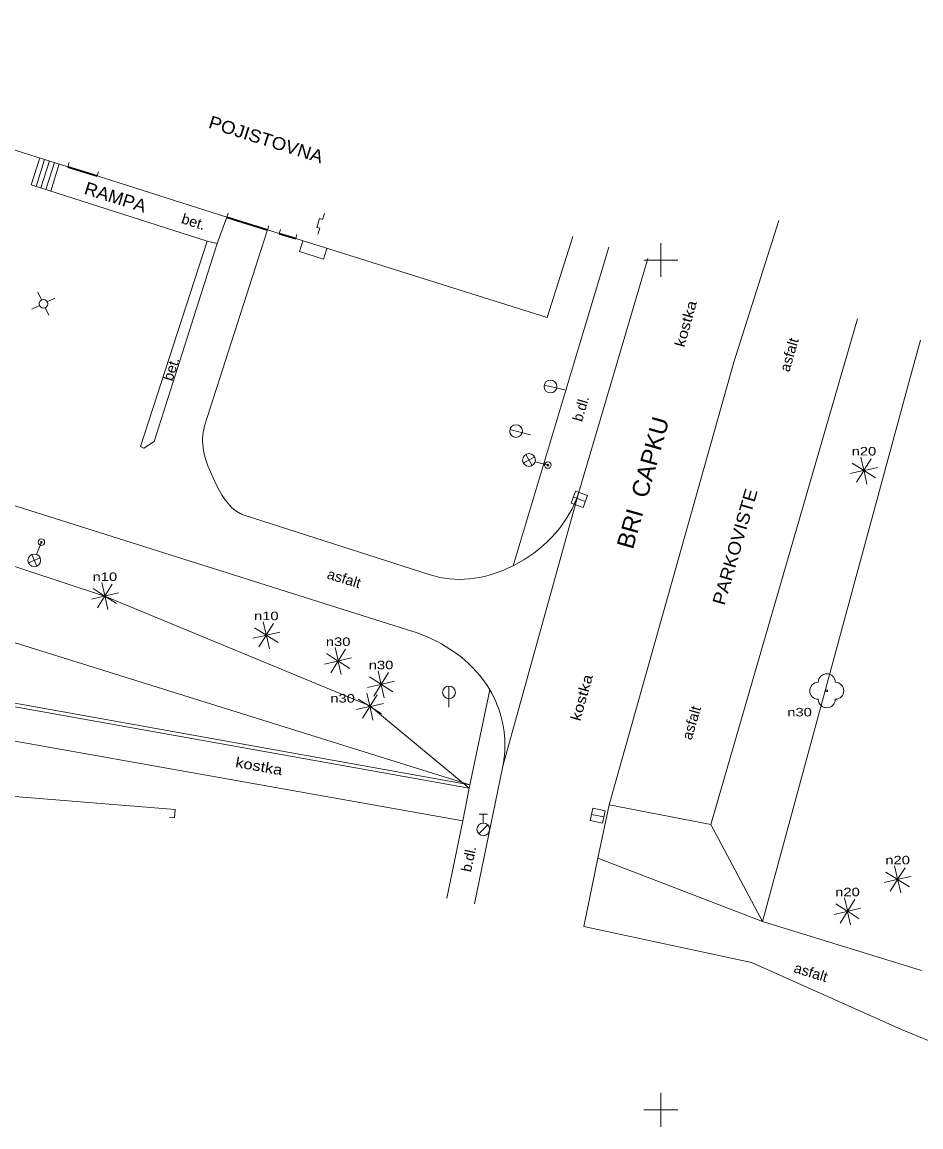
# Model space of a CAD drawing. Extents: x -670514 to -669423, y -1130798 to -1130123.
# Drawn here: x -670187.6 to -670134.7, y -1130251 to -1130186 of the extents above; entities that cross this region are included whole.
import ezdxf
from ezdxf.enums import TextEntityAlignment as Align

# ---------------------------------------------------------------- set-up
doc = ezdxf.new("R2010")
doc.units = 0
doc.header["$LTSCALE"] = 0.24
for name, color, linetype, lineweight in [('10', 7, 'Continuous', 13), ('11', 7, 'Continuous', 13), ('14', 7, 'Continuous', 13), ('22', 7, 'Continuous', 13), ('24', 7, 'Continuous', 13), ('27', 7, 'Continuous', 13), ('28', 7, 'Continuous', 13), ('31', 7, 'Continuous', 13), ('33', 7, 'Continuous', 13), ('45', 7, 'Continuous', 13), ('5', 7, 'Continuous', 13), ('6', 7, 'Continuous', 13), ('61', 7, 'Continuous', 13), ('9', 7, 'Continuous', 13)]:
    doc.layers.add(name, color=color, linetype=linetype, lineweight=lineweight)
for name, color, linetype in [('40', 7, 'Continuous'), ('41', 7, 'Continuous'), ('42', 7, 'Continuous')]:
    doc.layers.add(name, color=color, linetype=linetype)

msp = doc.modelspace()

# ---------------------------------------------------------------- linework, layer by layer
at = {"layer": '10'}
for p, q in [((-670186.532, -1130193.989), (-670187.033, -1130195.579)), ((-670186.245, -1130194.079), (-670186.746, -1130195.671)), ((-670185.959, -1130194.169), (-670186.461, -1130195.762)), ((-670185.673, -1130194.259), (-670186.175, -1130195.853)), ((-670185.387, -1130194.349), (-670185.89, -1130195.944)), ((-670176.687, -1130198.883), (-670187.033, -1130195.579)), ((-670173.137, -1130198.222), (-670176.84, -1130209.76)), ((-670153.056, -1130199.244), (-670154.502, -1130204.064)), ((-670150.763, -1130199.909), (-670152.213, -1130204.825)), ((-670138.43, -1130203.465), (-670139.173, -1130206.028)), ((-670154.502, -1130204.064), (-670158.68, -1130217.989)), ((-670152.213, -1130204.825), (-670154.821, -1130213.668)), ((-670164.577, -1130221.854), (-670216.254, -1130205.533)), ((-670139.173, -1130206.028), (-670147.058, -1130233.212)), ((-670174.503, -1130215.016), (-670163.562, -1130218.517)), ((-670190.705, -1130225.799), (-670161.27, -1130231.071)), ((-670160.061, -1130225.279), (-670161.27, -1130231.071)), ((-670190.834, -1130227.796), (-670161.644, -1130232.991)), ((-670160.957, -1130237.88), (-670159.28, -1130229.771)), ((-670153.024, -1130232.058), (-670147.058, -1130233.212)), ((-670162.586, -1130237.543), (-670161.644, -1130232.991))]:
    msp.add_line(p, q, dxfattribs=at)
for points in [[(-670180.604, -1130210.977), (-670176.687, -1130198.883), (-670176.091, -1130199.03), (-670175.528, -1130197.478)], [(-670180.604, -1130210.977), (-670180.416, -1130211.077), (-670179.812, -1130210.676), (-670176.091, -1130199.03)], [(-670154.526, -1130239.21), (-670153.696, -1130235.197), (-670153.024, -1130232.058)]]:
    msp.add_lwpolyline(points, dxfattribs=at)
for points in [[(-670176.84, -1130209.76), (-670176.921, -1130210.134), (-670176.254, -1130212.991), (-670174.734, -1130214.913), (-670174.503, -1130215.016)], [(-670163.562, -1130218.517), (-670163.28, -1130218.602), (-670158.68, -1130217.989), (-670154.944, -1130214.012), (-670154.821, -1130213.668)], [(-670164.577, -1130221.854), (-670164.092, -1130222.027), (-670160.061, -1130225.279), (-670159.179, -1130228.952), (-670159.28, -1130229.771)]]:
    msp.add_spline(points, degree=3, dxfattribs=at)
at = {"layer": '11'}
for p, q in [((-670143.047, -1130197.677), (-670145.702, -1130206.019)), ((-670145.702, -1130206.019), (-670153.024, -1130232.058)), ((-670154.821, -1130213.668), (-670159.28, -1130229.771)), ((-670161.27, -1130231.071), (-670161.644, -1130232.991))]:
    msp.add_line(p, q, dxfattribs=at)
at = {"layer": '14'}
for p, q in [((-670134.721, -1130204.715), (-670135.399, -1130207.213)), ((-670135.399, -1130207.213), (-670144.008, -1130238.917)), ((-670192.5, -1130221.111), (-670161.234, -1130230.874)), ((-670147.058, -1130233.212), (-670144.008, -1130238.917)), ((-670153.696, -1130235.197), (-670144.008, -1130238.917)), ((-670144.008, -1130238.917), (-670134.666, -1130241.791)), ((-670135.841, -1130245.268), (-670131.45, -1130247.085))]:
    msp.add_line(p, q, dxfattribs=at)
for points in [[(-670216.436, -1130208.635), (-670182.668, -1130219.789), (-670167.119, -1130226.229), (-670161.27, -1130231.071)], [(-670154.526, -1130239.21), (-670144.66, -1130241.33), (-670135.841, -1130245.268)]]:
    msp.add_lwpolyline(points, dxfattribs=at)
at = {"layer": '22'}
for p, q in [((-670138.079, -1130212.364), (-670138.735, -1130211.95)), ((-670138.053, -1130212.344), (-670138.225, -1130211.59)), ((-670137.611, -1130211.694), (-670138.025, -1130212.35)), ((-670138.839, -1130212.564), (-670138.085, -1130212.392)), ((-670138.065, -1130212.418), (-670138.479, -1130213.074)), ((-670138.037, -1130212.424), (-670137.865, -1130213.178)), ((-670137.355, -1130212.818), (-670138.011, -1130212.404)), ((-670138.005, -1130212.376), (-670137.251, -1130212.204)), ((-670182.736, -1130219.749), (-670183.392, -1130219.335)), ((-670182.71, -1130219.729), (-670182.882, -1130218.975)), ((-670182.268, -1130219.079), (-670182.682, -1130219.735)), ((-670183.496, -1130219.949), (-670182.742, -1130219.777)), ((-670182.722, -1130219.803), (-670183.136, -1130220.459)), ((-670182.694, -1130219.809), (-670182.522, -1130220.563)), ((-670182.012, -1130220.203), (-670182.668, -1130219.789)), ((-670182.662, -1130219.761), (-670181.908, -1130219.589)), ((-670173.214, -1130222.033), (-670173.386, -1130221.279)), ((-670173.24, -1130222.053), (-670173.896, -1130221.639)), ((-670172.772, -1130221.383), (-670173.186, -1130222.039)), ((-670173.166, -1130222.065), (-670172.412, -1130221.893)), ((-670174, -1130222.253), (-670173.246, -1130222.081)), ((-670173.226, -1130222.107), (-670173.64, -1130222.763)), ((-670173.198, -1130222.113), (-670173.026, -1130222.867)), ((-670172.516, -1130222.507), (-670173.172, -1130222.093)), ((-670169.012, -1130223.573), (-670169.668, -1130223.159)), ((-670168.986, -1130223.553), (-670169.158, -1130222.799)), ((-670168.544, -1130222.903), (-670168.958, -1130223.559)), ((-670169.772, -1130223.773), (-670169.018, -1130223.601)), ((-670168.998, -1130223.627), (-670169.412, -1130224.283)), ((-670168.97, -1130223.633), (-670168.798, -1130224.387)), ((-670168.288, -1130224.027), (-670168.944, -1130223.613)), ((-670168.938, -1130223.585), (-670168.184, -1130223.413)), ((-670166.486, -1130224.941), (-670167.142, -1130224.527)), ((-670166.46, -1130224.921), (-670166.632, -1130224.167)), ((-670166.018, -1130224.271), (-670166.432, -1130224.927)), ((-670167.246, -1130225.141), (-670166.492, -1130224.969)), ((-670166.472, -1130224.995), (-670166.886, -1130225.651)), ((-670166.444, -1130225.001), (-670166.272, -1130225.755)), ((-670165.762, -1130225.395), (-670166.418, -1130224.981)), ((-670166.412, -1130224.953), (-670165.658, -1130224.781)), ((-670167.143, -1130226.248), (-670167.799, -1130225.834)), ((-670167.117, -1130226.228), (-670167.289, -1130225.474)), ((-670166.675, -1130225.578), (-670167.089, -1130226.234)), ((-670167.903, -1130226.448), (-670167.149, -1130226.276)), ((-670167.129, -1130226.302), (-670167.543, -1130226.958)), ((-670167.101, -1130226.308), (-670166.929, -1130227.062)), ((-670166.419, -1130226.702), (-670167.075, -1130226.288)), ((-670167.069, -1130226.26), (-670166.315, -1130226.088)), ((-670136.096, -1130236.421), (-670136.752, -1130236.007)), ((-670136.07, -1130236.401), (-670136.242, -1130235.647)), ((-670135.628, -1130235.751), (-670136.042, -1130236.407)), ((-670136.856, -1130236.621), (-670136.102, -1130236.449)), ((-670136.082, -1130236.475), (-670136.496, -1130237.131)), ((-670136.054, -1130236.481), (-670135.882, -1130237.235)), ((-670135.372, -1130236.875), (-670136.028, -1130236.461)), ((-670136.022, -1130236.433), (-670135.268, -1130236.261)), ((-670139.02, -1130238.276), (-670139.192, -1130237.522)), ((-670139.046, -1130238.296), (-670139.702, -1130237.882)), ((-670138.578, -1130237.626), (-670138.992, -1130238.282)), ((-670138.972, -1130238.308), (-670138.218, -1130238.136)), ((-670139.806, -1130238.496), (-670139.052, -1130238.324)), ((-670139.032, -1130238.35), (-670139.446, -1130239.006)), ((-670139.004, -1130238.356), (-670138.832, -1130239.11)), ((-670138.322, -1130238.75), (-670138.978, -1130238.336))]:
    msp.add_line(p, q, dxfattribs=at)
for centre, radius in [((-670138.045, -1130212.384), 0.04), ((-670182.702, -1130219.769), 0.04), ((-670173.206, -1130222.073), 0.04), ((-670168.978, -1130223.593), 0.04), ((-670166.452, -1130224.961), 0.04), ((-670140.23, -1130225.344), 0.05), ((-670167.109, -1130226.268), 0.04), ((-670136.062, -1130236.441), 0.04), ((-670139.012, -1130238.316), 0.04)]:
    msp.add_circle(centre, radius, dxfattribs=at)
for centre, start, end in [((-670140.23, -1130224.844), 0, 180), ((-670140.73, -1130225.344), 90, 270), ((-670139.73, -1130225.344), 270, 90), ((-670140.23, -1130225.844), 180, 0)]:
    msp.add_arc(centre, 0.5, start, end, dxfattribs=at)
at = {"layer": '24'}
for points in [[(-670169.781, -1130197.258), (-670169.892, -1130197.609), (-670170.067, -1130197.554), (-670170.232, -1130198.081), (-670170.058, -1130198.136), (-670170.167, -1130198.488)], [(-670171.051, -1130198.871), (-670171.249, -1130199.5), (-670169.834, -1130199.944), (-670169.637, -1130199.314)]]:
    msp.add_lwpolyline(points, dxfattribs=at)
at = {"layer": '27'}
for p, q in [((-670156.851, -1130207.357), (-670155.634, -1130207.639)), ((-670158.873, -1130209.973), (-670157.66, -1130210.277)), ((-670155.137, -1130213.949), (-670154.433, -1130214.207)), ((-670162.457, -1130225.062), (-670162.457, -1130226.312)), ((-670154.078, -1130232.614), (-670153.344, -1130232.768))]:
    msp.add_line(p, q, dxfattribs=at)
for points in [[(-670155.266, -1130214.3), (-670154.562, -1130214.558), (-670154.303, -1130213.854), (-670155.008, -1130213.596)], [(-670154.155, -1130232.98), (-670153.421, -1130233.134), (-670153.267, -1130232.4), (-670154.001, -1130232.246)]]:
    msp.add_lwpolyline(points, close=True, dxfattribs=at)
for centre in [(-670156.4858, -1130207.4417), (-670158.5088, -1130210.0637), (-670162.4566, -1130225.4371)]:
    msp.add_circle(centre, 0.375, dxfattribs=at)
at = {"layer": '28'}
for p, q in [((-670160.691, -1130232.598), (-670160.191, -1130232.598)), ((-670160.441, -1130233.123), (-670160.441, -1130232.598)), ((-670160.706, -1130233.763), (-670160.176, -1130233.233))]:
    msp.add_line(p, q, dxfattribs=at)
msp.add_circle((-670160.441, -1130233.498), 0.375, dxfattribs=at)
at = {"layer": '31'}
for p, q in [((-670186.643, -1130201.898), (-670186.425, -1130202.351)), ((-670186.09, -1130202.466), (-670185.64, -1130202.25)), ((-670186.541, -1130202.684), (-670186.991, -1130202.901)), ((-670186.208, -1130202.799), (-670185.99, -1130203.252))]:
    msp.add_line(p, q, dxfattribs=at)
msp.add_circle((-670186.3156, -1130202.5757), 0.25, dxfattribs=at)
at = {"layer": '33'}
for p, q in [((-670157.564, -1130212.091), (-670157.939, -1130211.443)), ((-670158.076, -1130211.955), (-670157.427, -1130211.58)), ((-670156.64, -1130212.064), (-670157.388, -1130211.864)), ((-670186.437, -1130216.603), (-670186.719, -1130217.325)), ((-670186.706, -1130218.018), (-670187.006, -1130217.331)), ((-670186.513, -1130217.524), (-670187.199, -1130217.825))]:
    msp.add_line(p, q, dxfattribs=at)
for centre, radius in [((-670157.7509, -1130211.7668), 0.375), ((-670156.64, -1130212.064), 0.19), ((-670156.64, -1130212.064), 0.05), ((-670186.437, -1130216.603), 0.19), ((-670186.437, -1130216.603), 0.05), ((-670186.8556, -1130217.6741), 0.375)]:
    msp.add_circle(centre, radius, dxfattribs=at)
at = {"layer": '5'}
for p, q in [((-670211.898, -1130186.004), (-670184.876, -1130194.51)), ((-670183.16, -1130195.054), (-670175.528, -1130197.478)), ((-670173.137, -1130198.222), (-670172.443, -1130198.447)), ((-670171.474, -1130198.739), (-670156.672, -1130203.379)), ((-670155.176, -1130198.608), (-670156.672, -1130203.379)), ((-670178.563, -1130232.322), (-670191.833, -1130231.252)), ((-670178.603, -1130232.82), (-670178.563, -1130232.322)), ((-670178.902, -1130232.796), (-670178.603, -1130232.82))]:
    msp.add_line(p, q, dxfattribs=at)
at = {"layer": '6'}
for p, q in [((-670184.876, -1130194.51), (-670184.8, -1130194.271)), ((-670183.16, -1130195.054), (-670183.084, -1130194.816)), ((-670175.528, -1130197.478), (-670175.453, -1130197.239)), ((-670173.062, -1130197.983), (-670173.137, -1130198.222)), ((-670172.443, -1130198.447), (-670172.37, -1130198.207)), ((-670171.401, -1130198.499), (-670171.474, -1130198.739))]:
    msp.add_line(p, q, dxfattribs=at)
at = {"layer": '6', "lineweight": 35}
for p, q in [((-670184.876, -1130194.51), (-670183.16, -1130195.054)), ((-670175.528, -1130197.478), (-670173.137, -1130198.222)), ((-670172.443, -1130198.447), (-670171.474, -1130198.739))]:
    msp.add_line(p, q, dxfattribs=at)
at = {"layer": '61'}
for p, q in [((-670150, -1130201), (-670150, -1130199)), ((-670151, -1130200), (-670149, -1130200)), ((-670150, -1130251), (-670150, -1130249)), ((-670151, -1130250), (-670149, -1130250))]:
    msp.add_line(p, q, dxfattribs=at)
at = {"layer": '9'}
msp.add_line((-670190.669, -1130225.602), (-670161.234, -1130230.874), dxfattribs=at)

# ---------------------------------------------------------------- texts
at = {"layer": '22', "width": 1.3}
for s, p in [('n20', (-670138.0455, -1130211.498)), ('n10', (-670182.7025, -1130218.883)), ('n10', (-670173.2065, -1130221.187)), ('n30', (-670168.9785, -1130222.707)), ('n30', (-670166.4525, -1130224.075)), ('n30', (-670168.7155, -1130226.035)), ('n30', (-670141.8335, -1130226.851)), ('n20', (-670136.0625, -1130235.555)), ('n20', (-670139.0125, -1130237.43))]:
    msp.add_text(s, height=0.499, dxfattribs=at).set_placement(p, align=Align.CENTER)
at = {"layer": '40'}
for s, rotation, width, p in [('bet.', 342.289, 1.05, (-670177.5798, -1130198.0325)), ('kostka', 74.294, 1.2, (-670148.2426, -1130203.8297)), ('asfalt', 73.825, 1.05, (-670142.1562, -1130205.6606)), ('bet.', 72.281, 1.05, (-670178.5204, -1130206.4978)), ('asfalt', 342.893, 1.05, (-670168.7172, -1130219.0236)), ('kostka', 74.294, 1.2, (-670154.3636, -1130225.8217)), ('asfalt', 73.825, 1.05, (-670147.9052, -1130227.3116)), ('kostka', 349.909, 1.2, (-670173.6866, -1130230.0726)), ('asfalt', 342.9, 1.05, (-670141.2552, -1130242.1914))]:
    msp.add_text(s, height=0.6, rotation=rotation, dxfattribs=dict(at, width=width)).set_placement(p, align=Align.CENTER)
for rotation, p in [(73.568, (-670154.4187, -1130208.8249)), (78.316, (-670161.0047, -1130235.2963))]:
    msp.add_text('b.dl.', height=0.6, rotation=rotation, dxfattribs=at).set_placement(p, align=Align.CENTER)
at = {"layer": '41', "width": 1.1}
msp.add_text('POJISTOVNA', height=0.75, rotation=342.38, dxfattribs=at).set_placement((-670173.33, -1130193.2629), align=Align.CENTER)
at = {"layer": '42'}
for s, rotation, width, p in [('RAMPA', 342.476, 1.05, (-670182.1904, -1130196.6602)), ('PARKOVISTE', 73.825, 1.1, (-670145.2711, -1130216.971))]:
    msp.add_text(s, height=0.75, rotation=rotation, dxfattribs=dict(at, width=width)).set_placement(p, align=Align.CENTER)
at = {"layer": '45', "width": 1.05}
msp.add_text('BRI  CAPKU', height=1, rotation=74.294, dxfattribs=at).set_placement((-670150.5654, -1130213.2373), align=Align.CENTER)

doc.saveas('drawing.dxf')
